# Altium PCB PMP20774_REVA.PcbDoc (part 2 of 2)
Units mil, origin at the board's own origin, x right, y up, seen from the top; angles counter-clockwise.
Board outline 2225 x 750 mil, 4 copper layers (Top Layer, Signal Layer 1, Signal Layer 2, Bottom Layer), stack 61.2 mil thick; 80 components, 51 nets, 281 pads, 110 vias.
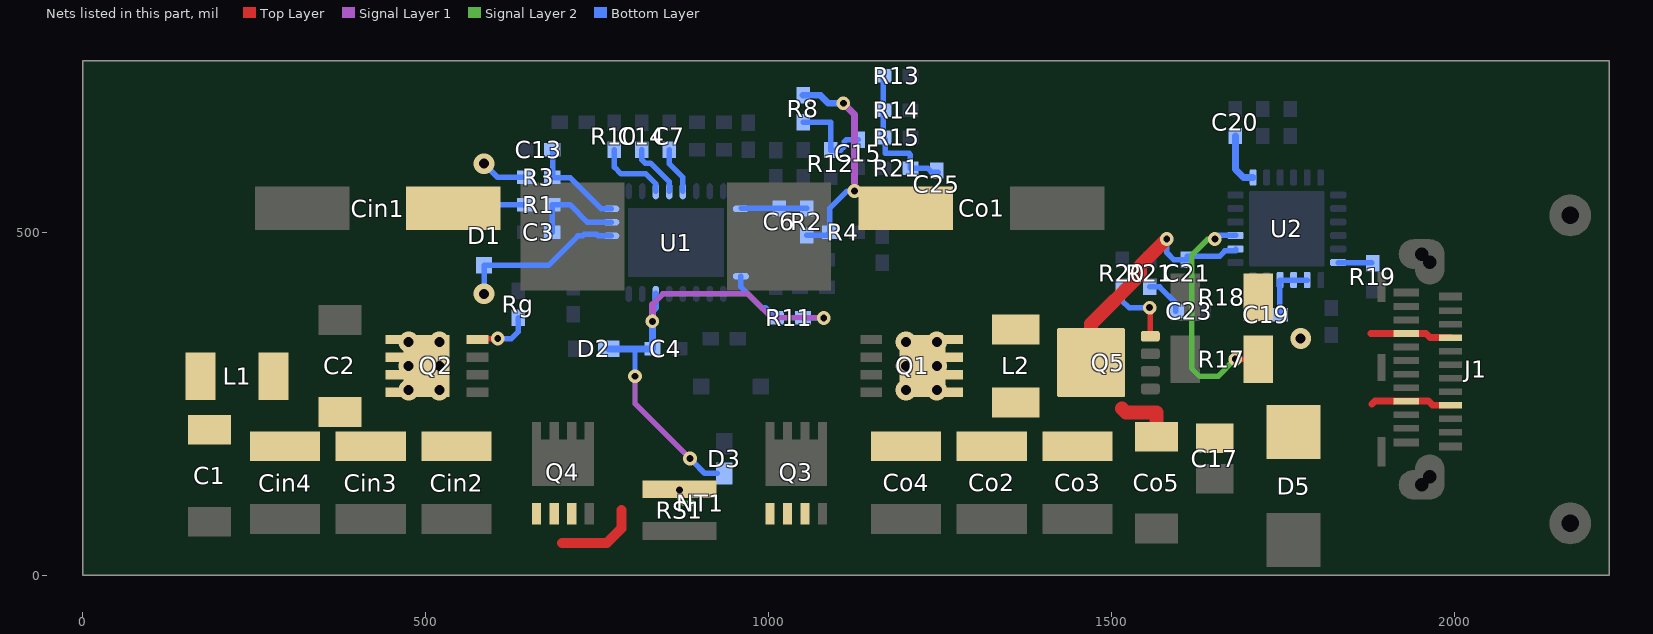
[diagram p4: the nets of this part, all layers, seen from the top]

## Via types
v1: diameter 30, hole 15, Top Layer to Bottom Layer, 56 vias
v2: diameter 20, hole 10, Top Layer to Bottom Layer, 51 vias
v3: diameter 16, hole 8, Top Layer to Bottom Layer, 2 vias
v4: diameter 16, hole 8, Top Layer to Bottom Layer, tented both sides, 1 vias

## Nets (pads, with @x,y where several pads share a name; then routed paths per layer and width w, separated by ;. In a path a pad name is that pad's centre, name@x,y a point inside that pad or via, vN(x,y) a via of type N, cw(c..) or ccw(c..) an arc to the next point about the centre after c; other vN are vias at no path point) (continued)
NetC15_1: C15.1 R8.2 R12.2 | length 131
  Bottom Layer w8: R8.2@1049.84,660.16 1089.84,660.16 1090,660.32 R12.2@1090,619.69 1104.69,619.69 1110,625 1110,631.75 1112.93,634.68 C15.1@1130,634.68
NetC20_1: C20.1 U2.1 | length 79.3
  Bottom Layer w10: C20.1@1680,640.32 1680,591.69 1691.89,579.8 U2.1@1705.79,579.8
NetC23_1: C23.1 R21.1@1555,420.32 | length 59.7
  Bottom Layer w8: R21.1@1555,420.32 1569.68,420.32 1593.07,396.93 C23.1@1593.07,385
NetC25_1: C25.1 R13.2 R14.2 R15.2 R21.2@1206.4,592.97 | length 214
  Bottom Layer w8: R13.2@1167.03,727.97 R14.2@1167.03,677.97 R15.2@1167.03,637.97 1170,635 1170,614.69 1204.37,614.69 1206.4,612.65 R21.2@1206.4,592.97 1231.72,592.97 1237.03,587.65 C25.1@1246.72,587.65
NetD1_1: D1.1 R1.2 | length 58.5
  Bottom Layer w8: D1.1@586.69,540 R1.2@645.16,540
NetQ2_4: Q2.4 Rg.2 | length 82.3
  Top Layer w8: Q2.4@577.15,345 v2(605,345)
  Bottom Layer w8: v2(605,345) 625,345 635,355 Rg.2@635,375.31
NetQ5_4: Q5.4 R20.2 | length 105
  Top Layer w8: Q5.4@1556.02,348.39 v2@1556.02,388.98
  Bottom Layer w8: R20.2@1515,420.31 1515,400 1525,390 v2(1555,390)
NetR19_1: R19.1 U2.12 | length 49.1
  Bottom Layer w8: U2.12@1829.8,455.79 R19.1@1878.9,455.79
PGOOD: R11.1 U1.14 | length 85
  Bottom Layer w8: U1.14@959.33,435.63 959.33,420.35 989.53,390.16 995.16,390.16 R11.1@1010.32,375
SLOPE: C14.1 U1.4 | length 81.7
  Bottom Layer w8: C14.1@814.84,620.16 814.84,605.72 819.84,600.72 827.57,600.72 855,573.28 U1.4@855,559.65
SS: C7.1 U1.5 | length 68.7
  Bottom Layer w8: C7.1@854.84,620.16 854.84,599.84 874.69,580 U1.5@874.69,559.65
SYNC: R10.2 U1.3 | length 106.7
  Bottom Layer w8: R10.2@774.84,620.16 774.84,594.84 784.84,584.84 820.99,584.84 835.32,570.52 U1.3@835.32,559.65
VAUX: C19.1 U2.14 U2.15 U2.16 | length 89.1
  Bottom Layer w8: C19.1@1744.68,380 U2.16@1744.68,429.72 ; U2.16@1745.16,430.2 U2.15@1764.84,430.2 U2.14@1784.53,430.2
VBAT: C2.1 Cin1.1 Cin2.1 Cin3.1 Cin4.1 D1.2 L1.2 Q2.5 Q2.6 Q2.7 Q2.8 Q2.9 R3.1 U1.26 | length 315.1
  Bottom Layer w8: v1(585,410) D1.2@585,451.69 678.79,451.69 721.78,494.68 728.75,494.68 730.94,496.87 749.06,496.87 751.25,494.68 U1.26@770.35,494.68 ; v1(585,600) 605,580 R3.1@645.16,580
  other v1: 475,270 520,270 475,305 520,305 475,340 520,340
VBUS: C17.1 D5.1 J1.A4 J1.A9 J1.B4 J1.B9 R17.2 R18.2 U2.21 | length 583.8
  Top Layer w8: v2(1679.68,315) R17.2@1713.15,315
  Top Layer w10: 1877.17,352.17 J1.A9@1928.74,352.17 1957.83,352.17 1963.74,346.26 J1.B4@1993.7,346.26 ; 1878.63,249.16 1883.21,253.74 J1.A4@1928.74,253.74 1961.26,253.74 1967.17,247.83 J1.B9@1993.7,247.83
  Signal Layer 2 w8: v2(1650,490) 1640,490 1616.22,466.22 1616.22,301.54 1627.76,290 1654.68,290 v2(1679.68,315)
  Bottom Layer w8: v2@1655.16,495.16 U2.21@1680.2,495.16
  other v1: 1775,345
VBUS_IN: C21.1 Co5.1 L2.2 Q5.5 Q5.6 Q5.7 Q5.8 Q5.9@1469.61,310 U2.20 | length 446.2
  Top Layer w20: Q5.9@1469.61,310 1469.61,366.42 1541.22,438.03 1541.22,451.22 v2(1580,490) ; 1514.69,243.07 1520.71,237.05 1565,237.05 Co5.1@1565,201.93
  Bottom Layer w8: v2(1580,490) 1580,470 1590.32,459.68 C21.1@1610,459.68 ; C21.1@1610,463.07 1610,465.26 1657.3,465.26 1664.62,472.58 1680.2,472.58 U2.20@1680.2,475.47
VCC: C4.1 D2.2 D3.2 R11.2 U1.20 | length 713.3
  Signal Layer 1 w8: v2(805,290) 805,250 v2@890,165 ; 830.32,394.68 845.63,410 969.68,410 1004.68,375 v2(1080,375)
  Signal Layer 1 w10: v2(830.32,370) 830.32,394.68
  Bottom Layer w8: v2(805,290) 805,330 ; v2@890,165 906.65,148.35 D3.2@925,148.35 ; R11.2@1049.69,375 v2(1080,375)
  Bottom Layer w10: D2.2@766.65,330 805,330 C4.1@830.32,330 v2(830.32,370) 830.32,384.92 ; 830.16,385.08 835.32,390.24 U1.20@835.32,410.04
  other v2: 885,170
VIN: C1.1 L1.1
VIN_IC: C3.1 R1.1 U1.27 | length 136.4
  Bottom Layer w8: C3.1@684.53,500 R1.1@684.53,540 710,540 735.63,514.37 U1.27@770.35,514.37
VINSNS: C13.2 R3.2 U1.28 | length 143.7
  Bottom Layer w8: C13.2@685.32,619.21 685.32,579.21 710.79,579.21 755.94,534.06 U1.28@770.35,534.06
VOSNS: C6.1 R2.1 U1.9 | length 95
  Bottom Layer w8: U1.9@959.96,534.68 C6.1@1015,534.68 R2.1@1055,534.68
VOUT: Co1.1 Co2.1 Co3.1 Co4.1 L2.1 Q1.5 Q1.6 Q1.7 Q1.8 Q1.9 R2.2 R4.2 R8.1 | length 315.6
  Signal Layer 1 w10: v2(1108.66,687.87) 1125,671.54 v2(1125,560)
  Bottom Layer w8: R2.2@1055,495.31 1084.29,495.31 R4.2@1088.98,500 1088.98,535 1113.98,560 v2(1125,560)
  Bottom Layer w10: R8.1@1049.84,699.53 1075.47,699.53 1087.13,687.87 v2(1108.66,687.87)
  other v1: 1200,270 1245,270 1200,305 1245,305 1200,340 1245,340
VRS: NT1.1 Q3.1 Q3.2 Q3.3 Q4.1 Q4.2 Q4.3 RS1.2 | length 158
  Top Layer w15: 699,47 764,47 785.2,68.2 785.2,95
  Signal Layer 2 w8: v2(870,124.11) 870,110 875,105 NT1.1@890,105
pads on no net: J1.A2 J1.A3 J1.A6 J1.A7 J1.A8 J1.A10 J1.A11 J1.B2 J1.B3 J1.B6 J1.B7 J1.B8 J1.B10 J1.B11 Q5.9@1448.74,271.61 Q5.9@1448.74,297.2 Q5.9@1448.74,322.8 Q5.9@1448.74,348.39 Q5.9@1467.54,283.92 Q5.9@1467.54,336.08 Q5.9@1482.11,310 Q5.9@1503.17,283.92 Q5.9@1503.17,336.08 U2.9 U2.10 U2.11 U2.25@1726.85,476.85 U2.25@1726.85,533.15 U2.25@1783.15,476.85 U2.25@1783.15,533.15

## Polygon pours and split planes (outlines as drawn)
GND on Top Layer "GND" (solid, remove dead copper, pour order 74): 0,750 0,0 2225,0 2225,750 0,750
VBUS on Top Layer "Vbus" (solid, remove dead copper, pour order 70): 1683,440.43 1683,340 1665.32,340 1660,334.68 1660,250 1613,250 1613,176 1699,176 1707,168 1707,140 1840,140 1840,300 1770,300 1770,440
ISNS on Top Layer "ISNS" (solid, remove dead copper, pour order 68): 1537,333 1537,263 1654,263 1654,356 1583.87,356 1581.26,353.39 1580,352.13 1580,333
VBAT on Top Layer "VBAT" (solid, remove dead copper, pour order 52): 233.81,395 235,393.82 235,350 240,345 239.88,213.74 239.88,145 244.88,150 600.12,150 600.12,219.88 595,225 565,255 565,275 565,390 620,390 620,667.4 620.47,667.87 618.35,670 445,670 445,310 330,310 330,395
VIN on Top Layer "Vin" (solid, remove dead copper, pour order 54): 0,445 0,245 135,245 135,150 230,150 230,340 230,445
HDRV1_N on Top Layer "HDRV1_N" (solid, remove dead copper, pour order 56): 630,670 630,460 605,435 574.39,404.39 574.39,257.76 574.39,250.61 620,205 620,75 620,110 625,115 770,115 770,360 800,390 803.03,393.03 803.03,661.5 797.13,661.5 788.62,670 630,670
VRS on Top Layer "VRS" (solid, remove dead copper, pour order 58): 620,110 762.93,110 770,117.07 775,122.07 775,140 946.5,140 947.72,138.78 947.72,102.28 1070,102.28 1070,70.2 959.61,70.2 931.72,86.28 785.2,95 785.2,70.2 755,40 620,40
HDRV2_N on Top Layer "HDRV2_N" (solid, remove dead copper, pour order 60): 953.07,115 1095,115 1095,230 1120,255 1145,255 1145,423.66 1108.66,460 1111.22,462.56 1111.22,670 936.5,670 936.5,131.57 953.07,115
VOUT on Top Layer "Vout" (solid, remove dead copper, pour order 62): 1125,668.19 1125,417.54 1149,393.54 1149,235 1122.05,235 1102,214.95 1100,212.95 1100,140 1475,140 1490,155 1490,215 1401,215 1401,293 1295,293 1295,445 1290,450 1290,665 1128.19,665
VBUS_IN on Top Layer "VBUS_IN" (solid, remove dead copper, pour order 64): 1315,405.08 1315,225 1525,225 1525,404.43 1524.35,405.08
GND on Signal Layer 1 "GND" (solid, remove dead copper, pour order 76): 0,745 0,0 2225,0 2225,750 0,750
GND on Signal Layer 2 "GND" (solid, remove dead copper, pour order 78): 0,750 0,0 2225,0 2225,750 0,750
GND on Bottom Layer "GND" (solid, remove dead copper, pour order 80): 0,750 0,0 2225,0 2225,750 0,750

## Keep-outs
Keep-Out Layer:
  text ".Layer_Name" at 577,-858.49 h60

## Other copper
Top Layer:
  rectangle net GND: 1160,720 1240,740
  rectangle net VBUS: 1831.81,325 1875,350
  rectangle net VBUS: 1770,283.61 1837.85,340
  rectangle net VBUS: 1760.43,340 1895,366.22
  rectangle net ISNS: 1544,267 1624.02,288
  rectangle net ISNS: 1544,288 1595,329
  rectangle net VBUS_IN: 1525,141 1606,245.06
  rectangle net VRS: 931,84 965,104
  rectangle net VBUS: 1823.5,215 1900,255
  rectangle net GND: 1015,720 1095,740
  text ".Layer_Name" at 577,-858.49 h60
Signal Layer 1:
  rectangle net HDRV1_N: 625,110 750,230
  rectangle net HDRV2_N: 970,105.32 1090,230
  rectangle net VOUT: 1155,235 1265,380
  rectangle net VBAT: 425,235 570,385
Signal Layer 2:
  rectangle net HDRV1_N: 625,94.68 770,229.68
  rectangle net HDRV2_N: 970,105.32 1090,230
  rectangle net VBAT: 425,238.07 570,385
  rectangle net VOUT: 1155,235 1265,380
Bottom Layer:
  rectangle net VOUT: 1155,235 1265,380
  rectangle net HDRV2_N: 973.07,105.32 1090,230
  rectangle net HDRV1_N: 625,95 770,230
  rectangle net VBAT: 425,234.13 570,384.13
  text ".Layer_Name" at 577,-858.49 h60

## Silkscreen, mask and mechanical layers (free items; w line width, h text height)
Top Overlay:
  text "'.PRJ_Number'.PCB_Rev-" at 1460,665 h80
  text ".Layer_Name" at 577,-858.49 h60
Bottom Overlay:
  region: 1740,235 1440,235 1440,135 1740,135
  text ".Layer_Name" at 577,-858.49 h60
Top Paste:
  text ".Layer_Name" at 577,-858.49 h60
Bottom Paste:
  text ".Layer_Name" at 577,-858.49 h60
Top Solder:
  rectangle: 15,70 105,215
  rectangle: 15,295 110,440
  text ".Layer_Name" at 577,-858.49 h60
  text ".Layer_Name" at 577,-858.49 h60
Bottom Solder:
  text ".Layer_Name" at 577,-858.49 h60
Drill Guide:
  text ".Layer_Name" at 577,-858.49 h60
M1 Board Outline:
  lines w10: 0,0 0,750 2225,750 2225,115 2225,0 0,0
  text ".Layer_Name" at 577,-858.49 h60
M2 Board Dimensions:
  rectangle: 125,-400 500,-275
  rectangle: 0,-275 125,-150
  lines w7: 0,-275 1000,-275 ; 125,-400 125,-150 ; 250,-400 250,-150 ; 500,-400 500,-150 ; 750,-400 750,-150 ; 0,-400 0,-150 1000,-150 1000,-400 0,-400
  text ".Layer_Name" at 577,-858.49 h60
M3 3D STEP Top:
  text ".Layer_Name" at 577,-858.49 h60
M4 3D STEP Bottom:
  text ".Layer_Name" at 577,-858.49 h60
M5 Assembly Top:
  lines w10: -292,-930.17 6308,-930.17 ; -292,-726.83 6310,-726.83 ; -292,-523.5 -292,-1133.5 3713,-1133.5 6310,-1133.5 6310,-523.5 -291.5,-523.5 -291.5,-1133.5 1284,-1133.5 ; 2173,-1133.5 2173,-523.5 ; 3440,-726.83 3440,-523.5 ; 4280,-726.83 4280,-523.5 ; 4902,-1140 4902,-937.17
  text "COMPONENTS MARKED 'DNP' SHOULD NOT BE POPULATED." at 1153.5,-318.5 h60
  text "ASSEMBLY VARIANT:" at 1153,-434 h60
  text ".VariantName" at 2189,-434 h60
  text "PCB VIEWED FROM TOP SIDE" at -228.5,-655.67 h60
  text "BOARD #:" at 2248,-655.67 h60
  text ".PRJ_Number" at 2793.5,-655.67 h60
  text "REV:" at 3638,-655.67 h60
  text ".PCB_Rev" at 3929.5,-655.67 h60
  text "SVN REV:" at 4476,-655.67 h60
  text ".VersionControl_RevNumber" at 4982,-655.67 h60
  text "TID #:" at 2248,-859 h60
  text ".TID" at 2793.5,-859 h60
  text "PLOT NAME =" at -228.5,-1064.34 h60
  text ".plot_File_Name" at 577,-1064.34 h60
  text "GENERATED    :" at 2250,-1064.34 h60
  text ".Print_Date" at 3119.5,-1064.34 h60
  text ".Print_Time" at 3848.5,-1064.34 h60
  text "TEXAS INSTRUMENTS" at 5113,-1064.34 h60
M6 Assembly Bottom:
  lines w10: -292.5,-727.33 6309.5,-727.33 ; -290.5,-930.67 6309.5,-930.67 ; 1115.5,-1140.5 1115.5,-937.67 ; 1737.5,-727.33 1737.5,-524 ; 2577.5,-727.33 2577.5,-524 ; 3844.5,-1134 3844.5,-524 ; 4733.5,-1134 6309,-1134 6309,-524 -292.5,-524 -292.5,-1134 2304.5,-1134 6309.5,-1134 6309.5,-524
  text "COMPONENTS MARKED 'DNP' SHOULD NOT BE POPULATED." at 6102,-318 h60
  text ".VariantName" at 5058,-434 h60
  text "ASSEMBLY VARIANT:" at 6097,-434 h60
  text ".VersionControl_RevNumber" at 1035.5,-656.17 h60
  text "SVN REV:" at 1541.5,-656.17 h60
  text ".PCB_Rev" at 2088,-656.17 h60
  text "REV:" at 2379.5,-656.17 h60
  text ".PRJ_Number" at 3224,-656.17 h60
  text "BOARD #:" at 3769.5,-656.17 h60
  text "PCB VIEWED FROM BOTTOM SIDE" at 6246,-656.17 h60
  text ".TID" at 3224,-859.5 h60
  text "TID #:" at 3769.5,-859.5 h60
  text "TEXAS INSTRUMENTS" at 904.5,-1064.84 h60
  text ".Print_Time" at 2169,-1064.84 h60
  text ".Print_Date" at 2898,-1064.84 h60
  text "GENERATED    :" at 3767.5,-1064.84 h60
  text ".plot_File_Name" at 5440.5,-1064.84 h60
  text "PLOT NAME =" at 6246,-1064.84 h60
M9 Title Sheet:
  drawing of 57 lines, arcs and shapes, not listed
  text "1" at 739.84,8036.5 h70
  text "2" at 3235.5,8036.5 h70
  text "3" at 5724.84,8036.5 h70
  text "4" at 8231.51,8036.5 h70
  text "5" at 10730.5,8036.5 h70
  text "6" at 13235.5,8036.5 h70
  text "A" at -416.5,6893.5 h70
  text "A" at 14383.5,6893.5 h70
  text "B" at -416.5,4513.5 h70
  text "B" at 14383.5,4513.5 h70
  text "C" at -416.5,2138.5 h70
  text "C" at 14383.5,2138.5 h70
  text "PROJECT TITLE:" at 11343.5,277.5 h45
  text ".PRJ_Title" at 11393.5,144.17 h70
  text "DESIGNED FOR:" at 11343.5,-23.5 h45
  text ".PRJ_Customer" at 11393.5,-163.5 h70
  text "D" at -416.5,-231.5 h70
  text "D" at 14383.5,-231.5 h70
  text "FILE NAME:" at 11343.5,-323.5 h45
  text ".PCB_File_Name_No_Path" at 11393.5,-443.5 h70
  text "Texas Instruments (TI) and/or its licensors do not warrant the accuracy or completeness of this specification" at 6374,-605.34 h45
  text "ENGINEER:" at 11343.5,-613.5 h45
  text "LAYOUT BY:" at 12848.5,-613.5 h45
  text "or any information contained therein. TI and/or its licensors do not warrant that this design will meet" at 6329.01,-718 h45
  text ".PRJ_Engineer" at 11393.5,-768.49 h70
  text ".PCB_Layout" at 12899,-768.49 h70
  text "the specifications, will be suitable for your application or fit for any particular purpose, or will operate in" at 6329.01,-830.67 h45
  text ".Layer_Name" at 577,-858.49 h60
  text "ALTIUM DESIGNER VERSION:" at 12848.5,-923.5 h45
  text "an implementation. TI and/or its licensors do not warrant that the design is production worthy. You should" at 6329.01,-943.33 h45
  text "completely validate and test your design implementation to confirm the system functionality for your application." at 6374,-1056 h45
  text ".print_Scale" at 11393.5,-1056.83 h70
  text ".Application_BuildNumber" at 12899,-1056.83 h70
  text "1" at 739.84,-1263.5 h70
  text "2" at 3235.5,-1263.5 h70
  text "3" at 5724.84,-1263.5 h70
  text "4" at 8231.51,-1263.5 h70
  text "5" at 10730.5,-1263.5 h70
  text "6" at 13235.5,-1263.5 h70
M10 Fab Notes:
  drawing of 173 lines, arcs and shapes, not listed
  text "DESIGN INFORMATION" at 12378.02,6201 h60
  text "MIN. TRACK WIDTH:" at 11733.46,6021 h60
  text "8" at 12829.7,6021 h60
  text "MIL" at 12984.46,6021 h60
  text "MIN. CLEARANCE:" at 11733.46,5889 h60
  text "0.2" at 12769.7,5889 h60
  text "mm" at 12984.46,5889 h60
  text "MIN. VIA PAD SIZE:" at 11733.46,5757 h60
  text "24" at 12799.71,5757 h60
  text "MIL" at 12984.46,5757 h60
  text "0.05mm (2MIL)" at 12428.46,5615.29 h60
  text "MINIMUM ANNULAR RING" at 11404.23,5611 h60
  text "EXTERNAL" at 13136.46,5611 h60
  text "PER" at 11604.23,5493 h60
  text "IPC-D-275 CLASS 2 LEVEL C" at 11824.23,5493 h60
  text "MIL, HOLES" at 13312.46,5380.71 h60
  text "+/-" at 12920,5380 h60
  text "+/-" at 13774,5380 h60
  text "REGISTRATION TOLERANCES:" at 11404.23,5375 h60
  text "METAL" at 12604,5375 h60
  text "5" at 13180.2,5375 h60
  text "3" at 14013.2,5375 h60
  text "MIL" at 14129.46,5375 h60
  text "+/-" at 13774,5262 h60
  text "HOLE SIZE TOLERANCE (UNLESS OTHERWISE SPECIFIED):" at 11404.23,5257 h60
  text "3" at 14013.2,5257 h60
  text "MIL" at 14129.46,5257 h60
  text "MATERIAL:" at 11329.46,5047.54 h60
  text "FR-4 High Tg" at 12315.9,4907.21 h60
  text "FR-408" at 11750.46,4898.64 h60
  text "OTHER" at 13238.46,4898.64 h60
  text "X" at 12161,4895 h60
  text "62 MIL (1.6mm) +/-10%" at 12070.56,4735.92 h60
  text "THICKNESS:" at 11404.23,4731.64 h60
  text "X" at 11942.4,4731.64 h60
  text "OTHER" at 13355.46,4731.64 h60
  text "TOLERANCE:" at 11404.23,4573.64 h60
  text "X" at 12243.53,4573.64 h60
  text "ANSI IPC-6012 TYPE 3 CLASS 2" at 12430.48,4573.64 h60
  text "OTHER +/-" at 12430.46,4417.64 h60
  text "BOW & TWIST:" at 11404.23,4260.64 h60
  text "X" at 12243.53,4260.64 h60
  text "ANSI IPC-6012 TYPE 3 CLASS 2" at 12430.48,4260.64 h60
  text "OTHER +/-" at 12430.46,4102.13 h60
  text "DRILLING:" at 11329.46,3963.64 h60
  text "REFERENCE:" at 11404.23,3846.64 h60
  text "X" at 12052.46,3846.64 h60
  text "AS SHOWN" at 12239.46,3846.64 h60
  text "X" at 12953.46,3846.64 h60
  text "NC_DRILL FILES" at 13090.46,3846.64 h60
  text "PTH COPPER THICKNESS:" at 11404.23,3688.64 h60
  text "X" at 12534.46,3688.64 h60
  text "20-30 um" at 12671.46,3688.64 h60
  text "OTHER" at 13388.46,3688.64 h60
  text "BOARD FINISH:" at 11329.46,3529.64 h60
  text "SILKSCREEN:" at 11484.68,3411.64 h60
  text "X" at 12433.46,3411.64 h60
  text "TOP" at 12559.46,3411.64 h60
  text "X" at 12943.46,3411.64 h60
  text "BOTTOM" at 13070.46,3411.64 h60
  text "SILKSCREEN COLOR:" at 11484.68,3244.64 h60
  text "X" at 12432.42,3244.64 h60
  text "WHITE" at 12559.46,3244.64 h60
  text "OTHER" at 13070.46,3244.64 h60
  text "X" at 12563.42,3085.44 h60
  text "GREEN" at 12690.46,3085.44 h60
  text "OTHER" at 13308.46,3085.44 h60
  text "SOLDER RESIST COLOR:" at 11484.68,3074.64 h60
  text "X" at 12563.42,2915.44 h60
  text "MATTE" at 12690.46,2915.44 h60
  text "SEMI-GLOSS" at 13308,2914.8 h60
  text "IMMERSION GOLD (ENIG)" at 12390.46,2726.92 h60
  text "ENEPIG" at 13728,2723.64 h60
  text "SURFACE FINISH:" at 11329.46,2722.64 h60
  text "X" at 12203.51,2722.64 h60
  text "IMM. TIN/SILVER OR EQUIV" at 11659,2565.64 h60
  text "OTHER" at 13090.46,2565.64 h60
  text "ARRAY/PANEL:" at 11329.46,2386.64 h60
  text "CUT AND TRIM PER M1 BOARD OUTLINE" at 12390.46,2382.35 h60
  text "N.C. ROUTE" at 12390.46,2230.64 h60
  text "X" at 13069.46,2230.64 h60
  text "V. SCORE" at 13256.46,2230.64 h60
  text "CERTIFICATION:" at 11329.46,2093.64 h60
  text "MATERIALS AND WORKMANSHIP FOR ALL PCBS" at 12054.46,2093.64 h60
  text "TO MEET OR EXCEED THE REQUIREMENTS OF:" at 12054.46,1995.64 h60
  text "X" at 11680.96,1859.13 h60
  text "ANSI IPC-A-600F CLASS ->" at 11819.96,1859.13 h60
  text "X" at 13459.02,1859.13 h60
  text "2" at 13577.96,1859.14 h60
  text "1" at 13262.96,1857.64 h60
  text "3" at 13931.96,1857.64 h60
  text "X" at 12495.02,1699.64 h60
  text "RoHS" at 12631.96,1699.64 h60
  text "OTHER" at 13276.36,1699.64 h60
  text "PER ORDER" at 13673.42,1699.64 h60
  text "ALL BOARDS MUST MEET OR EXCEED UL94-V0 REQUIREMENTS." at 11357,1534 h60
  text "PCB MUST BEAR THE UL94V-0 UL REGISTERED MATERIAL ID NUMBER" at 11357,1414 h60
  text "ADDITIONAL REQUIREMENTS:" at 11329.46,1240.64 h60
  text "MICROSECTION:" at 11404.23,1125.64 h60
  text "YES" at 12309.96,1125.64 h60
  text "REQUIRED" at 13171.46,969.49 h60
  text "BARE BOARD ELEC. TEST:" at 11404.23,966.64 h60
  text "NONE" at 12709.96,966.64 h60
  text "X" at 13044.46,966.64 h60
  text "PER ORDER" at 13763.46,966.64 h60
  text ".Layer_Name" at 577,-858.49 h60
M11 Gerber Information:
  lines w10: -292,-930.17 6308,-930.17 ; -292,-726.83 6310,-726.83 ; -292,-523.5 -292,-1133.5 3713,-1133.5 6310,-1133.5 6310,-523.5 -291.5,-523.5 -291.5,-1133.5 1284,-1133.5 ; 2173,-1133.5 2173,-523.5 ; 3440,-726.83 3440,-523.5 ; 4280,-726.83 4280,-523.5 ; 4902,-1140 4902,-937.17
  text "ALL ARTWORK VIEWED FROM TOP SIDE" at -228.5,-655.67 h60
  text "BOARD #:" at 2248,-655.67 h60
  text ".PRJ_Number" at 2793.5,-655.67 h60
  text "REV:" at 3638,-655.67 h60
  text ".PCB_Rev" at 3929.5,-655.67 h60
  text "SVN REV:" at 4476,-655.67 h60
  text ".VersionControl_RevNumber" at 4982,-655.67 h60
  text "LAYER NAME =" at -228.5,-858.49 h60
  text "TID #:" at 2248,-859 h60
  text ".TID" at 2793.5,-859 h60
  text "PLOT NAME =" at -228.5,-1064.34 h60
  text ".plot_File_Name" at 577,-1064.34 h60
  text "GENERATED    :" at 2250,-1064.34 h60
  text ".Print_Date" at 3119.5,-1064.34 h60
  text ".Print_Time" at 3848.5,-1064.34 h60
  text "TEXAS INSTRUMENTS" at 5113,-1064.34 h60
M12 Stackup:
  drawing of 400 lines, arcs and shapes, not listed
  text "Layer" at 4952.5,7615.8 h60
  text "Name" at 5362.41,7615.8 h60
  text "Material" at 6302.15,7615.8 h60
  text "Thickness" at 7161.92,7615.8 h60
  text "Constant" at 7811.76,7615.8 h60
  text "Board Layer Stack" at 8381.62,7615.8 h60
  text "1" at 4952.5,7495.8 h60
  text "Top Overlay" at 5362.41,7495.8 h60
  text "2" at 4952.5,7375.8 h60
  text "Top Solder" at 5362.41,7375.8 h60
  text "Solder Resist" at 6302.15,7375.8 h60
  text "0.40mil" at 7161.92,7375.8 h60
  text "3.5" at 7811.76,7375.8 h60
  text "3" at 4952.5,7255.8 h60
  text "Top Layer" at 5362.41,7255.8 h60
  text "Copper" at 6302.15,7255.8 h60
  text "1.40mil" at 7161.92,7255.8 h60
  text "4" at 4952.5,7135.8 h60
  text "Dielectric1" at 5362.41,7135.8 h60
  text "FR-4" at 6302.15,7135.8 h60
  text "20.00mil" at 7161.92,7135.8 h60
  text "4.8" at 7811.76,7135.8 h60
  text "5" at 4952.5,7015.8 h60
  text "Signal Layer 1" at 5362.41,7015.8 h60
  text "Copper" at 6302.15,7015.8 h60
  text "0.70mil" at 7161.92,7015.8 h60
  text "6" at 4952.5,6895.8 h60
  text "Dielectric2" at 5362.41,6895.8 h60
  text "FR-4" at 6302.15,6895.8 h60
  text "17.00mil" at 7161.92,6895.8 h60
  text "4.2" at 7811.76,6895.8 h60
  text "7" at 4952.5,6775.8 h60
  text "Signal Layer 2" at 5362.41,6775.8 h60
  text "Copper" at 6302.15,6775.8 h60
  text "0.70mil" at 7161.92,6775.8 h60
  text "8" at 4952.5,6655.8 h60
  text "Dielectric 3" at 5362.41,6655.8 h60
  text "FR-4" at 6302.15,6655.8 h60
  text "20.00mil" at 7161.92,6655.8 h60
  text "4.8" at 7811.76,6655.8 h60
  text "9" at 4952.5,6535.8 h60
  text "Bottom Layer" at 5362.41,6535.8 h60
  text "Copper" at 6302.15,6535.8 h60
  text "1.40mil" at 7161.92,6535.8 h60
  text "10" at 4952.5,6415.8 h60
  text "Bottom Solder" at 5362.41,6415.8 h60
  text "Solder Resist" at 6302.15,6415.8 h60
  text "0.40mil" at 7161.92,6415.8 h60
  text "3.5" at 7811.76,6415.8 h60
  text "11" at 4952.5,6295.8 h60
  text "Bottom Overlay" at 5362.41,6295.8 h60
  text ".Layer_Name" at 577,-858.49 h60
M13 Component Bodies Top:
  text ".Layer_Name" at 577,-858.49 h60
M14 Component Bodies Bottom:
  text ".Layer_Name" at 577,-858.49 h60
M15 Courtyards Top:
  text ".Layer_Name" at 577,-858.49 h60
M16 Courtyards Bottom:
  text ".Layer_Name" at 577,-858.49 h60
Drill Drawing:
  lines w10: 5336.14,2621.48 5391.46,2621.48 5391.46,2676.79 5336.14,2676.79 5336.14,2621.48 ; 5336.14,2801.25 5391.46,2801.25 5363.8,2745.93 5336.14,2801.25 ; 5336.14,2884.22 5349.97,2884.22 5363.8,2870.39 5377.63,2884.22 5391.46,2884.22 5377.63,2898.05 5391.46,2911.88 5377.63,2911.88 5363.8,2925.71 5349.97,2911.88 5336.14,2911.88 5349.97,2898.05 5336.14,2884.22 ; 5336.14,3008.68 5349.97,3008.68 5349.97,2994.85 5377.63,2994.85 5377.63,3008.68 5391.46,3008.68 5391.46,3036.34 5377.63,3036.34 5377.63,3050.17 5349.97,3050.17 5349.97,3036.34 5336.14,3036.34 5336.14,3008.68 ; 5336.14,3119.31 5363.8,3133.14 5391.46,3119.31 5377.63,3146.97 5391.46,3174.63 5363.8,3160.8 5336.14,3174.63 5349.97,3146.97 5336.14,3119.31 ; 5336.14,3243.77 5336.14,3257.6 5349.97,3271.43 5336.14,3285.26 5336.14,3299.08 5349.97,3299.08 5363.8,3285.26 5377.63,3299.08 5391.46,3299.08 5391.46,3285.26 5377.63,3271.43 5391.46,3257.6 5391.46,3243.77 5377.63,3243.77 5363.8,3257.6 5349.97,3243.77 5336.14,3243.77
  lines w12: 5286,2584.14 8518.76,2584.14 ; 5286,3330.89 8518.76,3330.89 ; 5624.17,2459.68 5624.17,3455.35 ; 5956.28,2459.68 5956.28,3455.35 ; 6593.29,2459.68 6593.29,3455.35 ; 6852.64,2459.68 6852.64,3455.35 ; 7228.06,2459.68 7228.06,3455.35 ; 7951.91,2459.68 7951.91,3455.35 ; 5286,2459.68 8518.76,2459.68 8518.76,3455.35 5286,3455.35 5286,2459.68
  text "Symbol" at 5360.68,3368.23 h72
  text "Quantity" at 5661.51,3368.23 h72
  text "Finished Hole Size" at 5993.62,3368.23 h72
  text "Plated" at 6630.62,3368.23 h72
  text "Hole Type" at 6889.98,3368.23 h72
  text "Drill Layer Pair" at 7265.4,3368.23 h72
  text "Hole Tolerance" at 7989.25,3368.23 h72
  text "3" at 5661.51,3243.77 h60
  text "8.00mil (0.203mm)" at 5993.62,3243.77 h60
  text "PTH" at 6630.62,3243.77 h60
  text "Round" at 6889.98,3243.77 h60
  text "Top Layer - Bottom Layer" at 7265.4,3243.77 h60
  text "51" at 5661.51,3119.31 h60
  text "10.00mil (0.254mm)" at 5993.62,3119.31 h60
  text "PTH" at 6630.62,3119.31 h60
  text "Round" at 6889.98,3119.31 h60
  text "Top Layer - Bottom Layer" at 7265.4,3119.31 h60
  text "56" at 5661.51,2994.85 h60
  text "15.00mil (0.381mm)" at 5993.62,2994.85 h60
  text "PTH" at 6630.62,2994.85 h60
  text "Round" at 6889.98,2994.85 h60
  text "Top Layer - Bottom Layer" at 7265.4,2994.85 h60
  text "2" at 5661.51,2870.39 h60
  text "25.59mil (0.650mm)" at 5993.62,2870.39 h60
  text "PTH" at 6630.62,2870.39 h60
  text "Round" at 6889.98,2870.39 h60
  text "Top Layer - Bottom Layer" at 7265.4,2870.39 h60
  text "2" at 5661.51,2745.93 h60
  text "19.69mil (0.500mm)" at 5993.62,2745.93 h60
  text "PTH" at 6630.62,2745.93 h60
  text "Slot" at 6889.98,2745.93 h60
  text "Top Layer - Bottom Layer" at 7265.4,2745.93 h60
  text "2" at 5661.51,2621.48 h60
  text "19.69mil (0.500mm)" at 5993.62,2621.48 h60
  text "PTH" at 6630.62,2621.48 h60
  text "Slot" at 6889.98,2621.48 h60
  text "Top Layer - Bottom Layer" at 7265.4,2621.48 h60
  text "116 Total" at 5661.51,2497.02 h60
  text "Slot definitions :" at 5360.68,2409.9 h60
  text "Routed Path Length" at 5811.08,2409.9 h60
  text "= Calculated from tool start centre position to tool end centre position." at 6350.29,2409.9 h60
  text "Hole Length" at 5811.08,2360.11 h60
  text "= Routed Path Length + Tool Size = Slot length as defined in the PCB layout" at 6150.69,2360.11 h60
  text ".Layer_Name" at 577,-858.49 h60
M17 Embedded Cavity:
  text ".Layer_Name" at 577,-858.49 h60
M18 Embedded Assembly:
  text ".Layer_Name" at 577,-858.49 h60
M19 Embedded Keepout:
  text ".Layer_Name" at 577,-858.49 h60

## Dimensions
0,0 to 2225,0 on M2 Board Dimensions
0,0 to 0,750 on M2 Board Dimensions
0,-400 to 1000,-400 on M2 Board Dimensions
